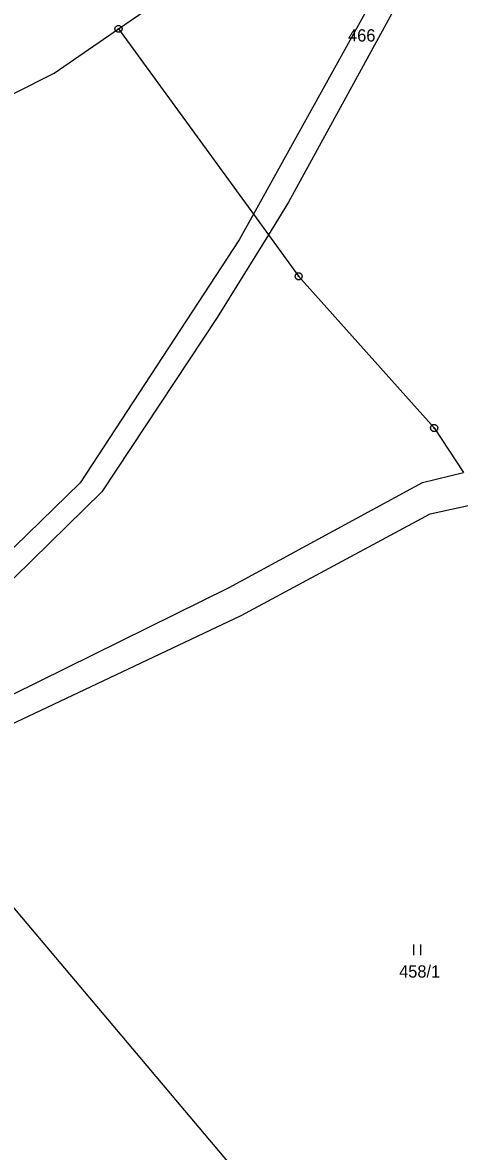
# Model space of a CAD drawing. Extents: x -694465 to -690527, y -983694 to -978978.
# Drawn here: x -692848.6 to -692787.9, y -980413.3 to -980256.5 of the extents above; entities that cross this region are included whole.
import ezdxf

# ---------------------------------------------------------------- set-up
doc = ezdxf.new("R2010")
doc.units = 0
for name, color, linetype in [('Vrstva 1', 7, 'Continuous'), ('Vrstva 18', 7, 'Continuous'), ('Vrstva 24', 7, 'Continuous'), ('Vrstva 25', 7, 'Continuous')]:
    doc.layers.add(name, color=color, linetype=linetype)

msp = doc.modelspace()

# ---------------------------------------------------------------- linework, layer by layer
at = {"layer": 'Vrstva 1'}
for points in [[(-692766.69, -980203.9), (-692792.13, -980239.083), (-692816.527, -980283.104)], [(-692764.321, -980206.702), (-692790.114, -980242.104), (-692811.628, -980281.442), (-692814.441, -980285.97)], [(-692835.26, -980257.37), (-692827.96, -980252.34)], [(-692844.17, -980263.51), (-692835.26, -980257.37)], [(-692835.26, -980257.37), (-692816.527, -980283.104)], [(-692902.954, -980293.173), (-692844.17, -980263.51)], [(-692816.527, -980283.104), (-692818.507, -980286.677), (-692840.561, -980320.425), (-692856.992, -980336.434), (-692874.842, -980348.799)], [(-692816.527, -980283.104), (-692814.441, -980285.97)], [(-692814.441, -980285.97), (-692821.573, -980297.451), (-692837.573, -980321.68), (-692857.031, -980340.718), (-692872.9, -980351.197)], [(-692814.441, -980285.97), (-692810.24, -980291.74)], [(-692810.24, -980291.74), (-692791.43, -980312.81)], [(-692791.43, -980312.81), (-692787.34, -980318.98)], [(-692793.03, -980320.39), (-692787.34, -980318.98)], [(-692819.91, -980334.97), (-692793.03, -980320.39)], [(-692791.96, -980324.74), (-692784.55, -980323.14)], [(-692818.2, -980338.86), (-692791.96, -980324.74)], [(-692853.84, -980351.73), (-692819.91, -980334.97)], [(-692852.1, -980354.9), (-692818.2, -980338.86)], [(-692817.32, -980417.95), (-692854.7, -980373.68)]]:
    msp.add_lwpolyline(points, dxfattribs=at)
at = {"layer": 'Vrstva 24'}
for points in [[(-692835.106, -980256.894), (-692834.856, -980257.076), (-692834.76, -980257.37), (-692834.856, -980257.664), (-692835.106, -980257.846), (-692835.414, -980257.846), (-692835.664, -980257.664), (-692835.76, -980257.37), (-692835.664, -980257.076), (-692835.414, -980256.894)], [(-692835.106, -980256.894), (-692834.856, -980257.076), (-692834.76, -980257.37), (-692834.856, -980257.664), (-692835.106, -980257.846), (-692835.414, -980257.846), (-692835.664, -980257.664), (-692835.76, -980257.37), (-692835.664, -980257.076), (-692835.414, -980256.894)], [(-692810.086, -980291.264), (-692809.836, -980291.446), (-692809.74, -980291.74), (-692809.836, -980292.034), (-692810.086, -980292.216), (-692810.394, -980292.216), (-692810.644, -980292.034), (-692810.74, -980291.74), (-692810.644, -980291.446), (-692810.394, -980291.264)], [(-692791.276, -980312.334), (-692791.026, -980312.516), (-692790.93, -980312.81), (-692791.026, -980313.104), (-692791.276, -980313.286), (-692791.584, -980313.286), (-692791.834, -980313.104), (-692791.93, -980312.81), (-692791.834, -980312.516), (-692791.584, -980312.334)]]:
    msp.add_lwpolyline(points, close=True, dxfattribs=at)
for points in [[(-692835.379, -980257.37), (-692835.14, -980257.37)], [(-692835.379, -980257.37), (-692835.14, -980257.37)], [(-692810.359, -980291.74), (-692810.12, -980291.74)], [(-692791.549, -980312.81), (-692791.31, -980312.81)]]:
    msp.add_lwpolyline(points, dxfattribs=at)
at = {"layer": 'Vrstva 25'}
for points in [[(-692794.27, -980384.56), (-692794.27, -980386.06)], [(-692793.27, -980386.06), (-692793.27, -980384.56)]]:
    msp.add_lwpolyline(points, dxfattribs=at)

# ---------------------------------------------------------------- texts
at = {"layer": 'Vrstva 18'}
for s, p in [('466', (-692803.373, -980259.13)), ('458/1', (-692796.283, -980389.16))]:
    msp.add_text(s, height=1.7, dxfattribs=at).set_placement(p)

doc.saveas('drawing.dxf')
